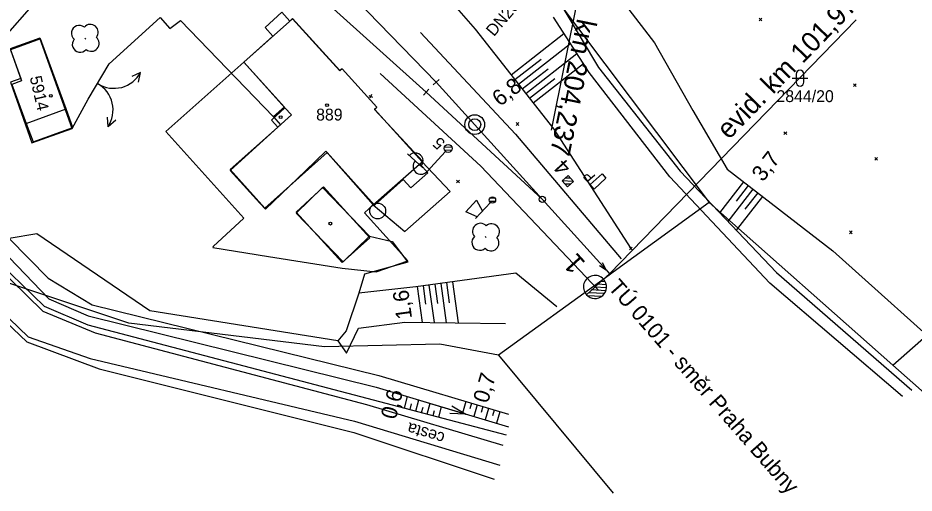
# Model space of a CAD drawing. Extents: x -800194 to -799078, y -1007177 to -1006597.
# Drawn here: x -799787.9 to -799674.6, y -1007068 to -1007007.9 of the extents above; entities that cross this region are included whole.
import ezdxf

# ---------------------------------------------------------------- set-up
doc = ezdxf.new("R2010")
doc.units = 0
for name, color, linetype in [('02_Osa_koleje', 7, 'Continuous'), ('_návrh', 7, 'Continuous'), ('Vrstva 11', 7, 'Continuous'), ('Vrstva 13', 7, 'Continuous'), ('Vrstva 17', 7, 'Continuous'), ('Vrstva 2', 7, 'Continuous'), ('Vrstva 23', 7, 'Continuous'), ('Vrstva 25', 7, 'Continuous'), ('Vrstva 3', 7, 'Continuous'), ('Vrstva 33', 7, 'Continuous'), ('Vrstva 4', 7, 'Continuous'), ('Vrstva 43', 7, 'Continuous'), ('Vrstva 48', 7, 'Continuous'), ('Vrstva 49', 7, 'Continuous'), ('Vrstva 5', 7, 'Continuous'), ('Vrstva 50', 7, 'Continuous'), ('Vrstva 51', 7, 'Continuous'), ('Vrstva 55', 7, 'Continuous'), ('Vrstva 56', 7, 'Continuous'), ('Vrstva 57', 7, 'Continuous'), ('Vrstva 58', 7, 'Continuous'), ('Vrstva 59', 7, 'Continuous'), ('Vrstva 7', 7, 'Continuous')]:
    doc.layers.add(name, color=color, linetype=linetype)

msp = doc.modelspace()

# ---------------------------------------------------------------- linework, layer by layer
at = {"layer": '_návrh'}
for points in [[(-799821.59, -1006948.01), (-799811.06, -1006954.32), (-799803.75, -1006958.71), (-799793.94, -1006964.58), (-799784.22, -1006971.67), (-799782.91, -1006972.63), (-799767.42, -1006984.72), (-799752.33, -1006998.17), (-799735.03, -1007016), (-799721.62, -1007030.81), (-799713.56, -1007039.73), (-799713.11, -1007040.22)], [(-799820.76, -1006954), (-799803, -1006964.74), (-799786.68, -1006975.32), (-799769.88, -1006987.81), (-799754.74, -1007000.64), (-799736.31, -1007017.26), (-799721.62, -1007030.81)]]:
    msp.add_lwpolyline(points, dxfattribs=at)
at = {"layer": 'Vrstva 11'}
for p, q in [((-799717.7, -1007028.56), (-799719.11, -1007028.49)), ((-799718.09, -1007028.91), (-799718.75, -1007028.88)), ((-799718.05, -1007028.16), (-799718.72, -1007028.13))]:
    msp.add_line(p, q, dxfattribs=at)
msp.add_lwpolyline([(-799718.44, -1007029.23), (-799719.11, -1007028.48), (-799718.37, -1007027.81), (-799717.69, -1007028.56)], close=True, dxfattribs=at)
at = {"layer": 'Vrstva 13'}
msp.add_line((-799737.02, -1007056.24), (-799731.27, -1007057.97), dxfattribs=at)
for points in [[(-799805.07, -1007021.46), (-799784.01, -1007043.38), (-799779.03, -1007045.56), (-799742.64, -1007054.55), (-799725.89, -1007059.59)], [(-799733.04, -1007056.92), (-799731.27, -1007057.97), (-799733.33, -1007057.88)]]:
    msp.add_lwpolyline(points, dxfattribs=at)
at = {"layer": 'Vrstva 17'}
for p, q in [((-799779.06, -1007018.13), (-799776.39, -1007013.67)), ((-799781.07, -1007021.85), (-799779.06, -1007018.13)), ((-799738.62, -1007038.76), (-799744.11, -1007040.3))]:
    msp.add_line(p, q, dxfattribs=at)
for points in [[(-799828.95, -1007006.88), (-799820.58, -1007016.71), (-799786.81, -1007048.82), (-799777.64, -1007052.25), (-799745.45, -1007060.29), (-799727.71, -1007066.19)], [(-799776.39, -1007013.67), (-799769.93, -1007007.83), (-799768.72, -1007009.2), (-799767.36, -1007008.22), (-799755.62, -1007020.4)], [(-799744.11, -1007040.3), (-799744.8, -1007042.69), (-799746.42, -1007047.46), (-799747.49, -1007048.69), (-799771.23, -1007044.93), (-799785.53, -1007035.2), (-799789.01, -1007035.75), (-799804.25, -1007020.27), (-799801.55, -1007019.07), (-799803.93, -1007010.19)], [(-799772.68, -1007016.01), (-799772.41, -1007014.78), (-799773.52, -1007015.27)], [(-799775.56, -1007020.82), (-799776.52, -1007021.64), (-799776.61, -1007020.42)], [(-799743.45, -1007035.49), (-799740.6, -1007036.15), (-799738.62, -1007038.76)]]:
    msp.add_lwpolyline(points, dxfattribs=at)
for centre, start, end in [((-799775.78, -1007012.95), 238.0469, 331.5667), ((-799779.72, -1007019.53), 326.5964, 60.1163)]:
    msp.add_arc(centre, 3.83, start, end, dxfattribs=at)
at = {"layer": 'Vrstva 2'}
for p, q in [((-799713.11, -1007040.22), (-799681.94, -1007008.13)), ((-799735.4, -1007016.33), (-799734.66, -1007015.66)), ((-799735.97, -1007016.89), (-799736.65, -1007017.63)), ((-799713.88, -1007040.92), (-799713.11, -1007040.22)), ((-799716.05, -1007042.88), (-799713.88, -1007040.92)), ((-799713.67, -1007041.23), (-799714.19, -1007041.2)), ((-799713.58, -1007042.37), (-799715.39, -1007042.28)), ((-799713.51, -1007041.99), (-799714.99, -1007041.92)), ((-799713.53, -1007041.61), (-799714.59, -1007041.56)), ((-799716.05, -1007042.88), (-799716.05, -1007042.88)), ((-799714.14, -1007043.1), (-799715.91, -1007043.02)), ((-799713.77, -1007042.74), (-799715.79, -1007042.64))]:
    msp.add_line(p, q, dxfattribs=at)
msp.add_lwpolyline([(-799714.4, -1007039.18), (-799713.56, -1007039.73), (-799714.01, -1007038.84)], dxfattribs=at)
msp.add_circle((-799721.62, -1007030.81), 0.4, dxfattribs=at)
for start, end in [(42.0718, 222.5413), (222.1613, 42.1222)]:
    msp.add_arc((-799714.96, -1007041.9), 1.46, start, end, dxfattribs=at)
at = {"layer": 'Vrstva 23'}
for points in [[(-799756.7, -1007031.95), (-799748.82, -1007024.88), (-799742.83, -1007031.56), (-799739.2, -1007028.31), (-799738.26, -1007029.36), (-799736.11, -1007027.47), (-799737.08, -1007026.37), (-799736.71, -1007026.05), (-799742.83, -1007019.45), (-799742.53, -1007019.18), (-799746.94, -1007014.31), (-799747.2, -1007014.54), (-799753.19, -1007007.93), (-799753.56, -1007008.27), (-799754.56, -1007007.16), (-799756.67, -1007009.07), (-799755.68, -1007010.17), (-799759.34, -1007013.45), (-799754.23, -1007019.15), (-799755.62, -1007020.4), (-799754.74, -1007021.39), (-799761.08, -1007027.06), (-799756.7, -1007031.95)], [(-799785.14, -1007010.44), (-799788.91, -1007011.78), (-799787.56, -1007015.55), (-799788.88, -1007016.02), (-799786.16, -1007023.66), (-799781.07, -1007021.85), (-799785.14, -1007010.44)], [(-799746.8, -1007038.73), (-799743.45, -1007035.49), (-799749.4, -1007029.33), (-799752.76, -1007032.58), (-799746.8, -1007038.73)]]:
    msp.add_lwpolyline(points, dxfattribs=at)
at = {"layer": 'Vrstva 25'}
for p, q in [((-799733.05, -1007024.22), (-799734, -1007024.26)), ((-799736.74, -1007026.84), (-799738.65, -1007025.08)), ((-799733.86, -1007024.75), (-799736.23, -1007027.32)), ((-799733.07, -1007024.59), (-799733.95, -1007024.63))]:
    msp.add_line(p, q, dxfattribs=at)
msp.add_circle((-799733.52, -1007024.38), 0.5, dxfattribs=at)
for centre, start, end in [((-799737.69, -1007025.95), 316.6332, 138.0383), ((-799736.96, -1007026.64), 137.3357, 317.3357)]:
    msp.add_arc(centre, 1, start, end, dxfattribs=at)
at = {"layer": 'Vrstva 3'}
msp.add_line((-799769.88, -1006987.81), (-799828.64, -1007054.5), dxfattribs=at)
at = {"layer": 'Vrstva 33'}
for p, q in [((-799731.31, -1007032.4), (-799729.95, -1007030.92)), ((-799730.07, -1007033.26), (-799728.18, -1007031.21)), ((-799729.95, -1007030.92), (-799729.19, -1007032.31)), ((-799727.59, -1007030.68), (-799728.27, -1007030.7)), ((-799727.56, -1007031.08), (-799728.26, -1007031.1)), ((-799729.86, -1007033.04), (-799731.31, -1007032.4))]:
    msp.add_line(p, q, dxfattribs=at)
for points in [[(-799716.27, -1007028.19), (-799716.34, -1007028.04), (-799716.26, -1007027.82), (-799716.18, -1007027.75), (-799715.95, -1007027.69), (-799715.81, -1007027.78)], [(-799714.99, -1007027.74), (-799715.92, -1007028.58)], [(-799715.81, -1007027.78), (-799715.46, -1007028.16)], [(-799715.92, -1007028.58), (-799716.27, -1007028.19)]]:
    msp.add_lwpolyline(points, dxfattribs=at)
msp.add_lwpolyline([(-799715.07, -1007029.52), (-799715.56, -1007028.96), (-799714.07, -1007027.61), (-799713.57, -1007028.16)], close=True, dxfattribs=at)
msp.add_circle((-799727.92, -1007030.9), 0.401, dxfattribs=at)
at = {"layer": 'Vrstva 4'}
for points in [[(-799737.02, -1007009.7), (-799725.03, -1007022.56), (-799711.65, -1007038.33)], [(-799742.12, -1007014.91), (-799729.41, -1007026.63), (-799714.56, -1007042.27)]]:
    msp.add_lwpolyline(points, dxfattribs=at)
at = {"layer": 'Vrstva 43'}
msp.add_circle((-799742.43, -1007032.29), 1, dxfattribs=at)
at = {"layer": 'Vrstva 48'}
for p, q in [((-799725.54, -1007015.08), (-799718.88, -1007009.85)), ((-799724.62, -1007016.26), (-799718.06, -1007011.11)), ((-799725.08, -1007015.67), (-799721.77, -1007013.08)), ((-799723.69, -1007017.44), (-799717.24, -1007012.38)), ((-799722.77, -1007018.62), (-799716.42, -1007013.64)), ((-799724.16, -1007016.85), (-799720.9, -1007014.3)), ((-799723.23, -1007018.03), (-799720.03, -1007015.52)), ((-799696.17, -1007028.6), (-799699.2, -1007032.52)), ((-799694.99, -1007029.52), (-799698.16, -1007033.62)), ((-799695.58, -1007029.06), (-799697.13, -1007031.06)), ((-799694.39, -1007029.98), (-799696.01, -1007032.07)), ((-799693.8, -1007030.44), (-799697.11, -1007034.72)), ((-799733.72, -1007041.35), (-799733.38, -1007043.89)), ((-799732.98, -1007041.25), (-799732.28, -1007046.44)), ((-799737.44, -1007041.85), (-799736.82, -1007046.39)), ((-799736.69, -1007041.75), (-799736.38, -1007044.08)), ((-799735.95, -1007041.65), (-799735.31, -1007046.41)), ((-799735.21, -1007041.55), (-799734.88, -1007043.98)), ((-799734.46, -1007041.45), (-799733.79, -1007046.42)), ((-799739.06, -1007057.21), (-799738.67, -1007055.75)), ((-799738.33, -1007057.41), (-799738.14, -1007056.68)), ((-799737.61, -1007057.6), (-799737.23, -1007056.18)), ((-799736.88, -1007057.79), (-799736.7, -1007057.09)), ((-799736.16, -1007057.98), (-799735.8, -1007056.61)), ((-799734.71, -1007058.36), (-799734.36, -1007057.04)), ((-799731.29, -1007056.39), (-799731.72, -1007057.84)), ((-799730.57, -1007056.61), (-799730.79, -1007057.33)), ((-799729.85, -1007056.82), (-799730.28, -1007058.27)), ((-799729.13, -1007057.03), (-799729.35, -1007057.76)), ((-799728.42, -1007057.25), (-799728.85, -1007058.7)), ((-799735.43, -1007058.17), (-799735.25, -1007057.5)), ((-799727.7, -1007057.46), (-799727.91, -1007058.19)), ((-799726.98, -1007057.68), (-799727.41, -1007059.13))]:
    msp.add_line(p, q, dxfattribs=at)
at = {"layer": 'Vrstva 49'}
for p, q in [((-799694.21, -1007007.89), (-799693.85, -1007008.25)), ((-799694.21, -1007008.25), (-799693.85, -1007007.89)), ((-799682.29, -1007016.19), (-799681.94, -1007016.54)), ((-799682.29, -1007016.54), (-799681.94, -1007016.19)), ((-799743.22, -1007017.57), (-799743.43, -1007018.03)), ((-799743.55, -1007017.7), (-799743.1, -1007017.9)), ((-799724.92, -1007021.1), (-799724.57, -1007021.46)), ((-799724.92, -1007021.46), (-799724.57, -1007021.1)), ((-799720.16, -1007021.94), (-799710.42, -1007037.04)), ((-799691.07, -1007022.28), (-799690.71, -1007022.63)), ((-799691.07, -1007022.63), (-799690.71, -1007022.28)), ((-799679.59, -1007025.51), (-799679.23, -1007025.86)), ((-799679.59, -1007025.86), (-799679.23, -1007025.51)), ((-799732.47, -1007028.39), (-799732.11, -1007028.74)), ((-799732.47, -1007028.74), (-799732.11, -1007028.39)), ((-799682.8, -1007034.8), (-799682.45, -1007035.16)), ((-799682.8, -1007035.16), (-799682.45, -1007034.8)), ((-799710.6, -1007036.86), (-799710.25, -1007037.22)), ((-799710.6, -1007037.22), (-799710.25, -1007036.86))]:
    msp.add_line(p, q, dxfattribs=at)
for points in [[(-799823.43, -1006985.38), (-799817.84, -1006990.05), (-799815.5, -1006993.97), (-799810.13, -1006998.91), (-799803.93, -1007010.19), (-799801.55, -1007019.07), (-799804.25, -1007020.27), (-799789.01, -1007035.75), (-799784.1, -1007040.77), (-799778.54, -1007044.17), (-799742.31, -1007053.11), (-799725.9, -1007058)], [(-799823.43, -1006985.38), (-799822.82, -1006995.38), (-799809.85, -1007012.44), (-799805.07, -1007021.46), (-799784.01, -1007043.38), (-799779.03, -1007045.56), (-799742.64, -1007054.55), (-799725.89, -1007059.59)], [(-799822.82, -1006995.38), (-799817.69, -1007012.45), (-799816.63, -1007013.29), (-799784.59, -1007044.32), (-799779.07, -1007046.68), (-799743, -1007056.17), (-799726.2, -1007060.6)], [(-799716.25, -1006997.26), (-799711.44, -1007004.24), (-799711.11, -1007006.25), (-799707.44, -1007011.02), (-799702.58, -1007019.59), (-799698.24, -1007027), (-799684.87, -1007037.35), (-799668.9, -1007051.67)], [(-799733.04, -1007005.94), (-799730.09, -1007009.29), (-799720.16, -1007021.94)], [(-799718.91, -1007006.79), (-799714.52, -1007014.16), (-799704.21, -1007027.24), (-799692.02, -1007040.08), (-799674.89, -1007054.95)], [(-799676.08, -1007055.76), (-799692.87, -1007041.41), (-799705.48, -1007027.95), (-799715.68, -1007014.78), (-799720.21, -1007007.79)], [(-799719.8, -1007044.43), (-799724.97, -1007040.17), (-799737.6, -1007041.88), (-799744.8, -1007042.69), (-799746.42, -1007047.46), (-799747.49, -1007048.69), (-799746.37, -1007050.25)], [(-799746.37, -1007050.25), (-799744.87, -1007047.1), (-799739.02, -1007046.37), (-799726.29, -1007046.5)]]:
    msp.add_lwpolyline(points, dxfattribs=at)
at = {"layer": 'Vrstva 5'}
msp.add_line((-799720.48, -1007022.09), (-799714.57, -1006992.8), dxfattribs=at)
at = {"layer": 'Vrstva 50'}
for p, q in [((-799779.46, -1007010.42), (-799779.35, -1007010.51)), ((-799728.74, -1007035.63), (-799728.83, -1007035.53))]:
    msp.add_line(p, q, dxfattribs=at)
for centre, start, end in [((-799780.17, -1007009.81), 49.7024, 229.7024), ((-799778.76, -1007009.69), 319.7024, 139.7024), ((-799780.05, -1007011.22), 139.7024, 319.7024), ((-799778.65, -1007011.1), 229.7024, 49.7024), ((-799729.45, -1007034.85), 42.1413, 222.1413), ((-799728.04, -1007034.92), 312.1413, 132.1413), ((-799729.52, -1007036.26), 132.1413, 312.1413), ((-799728.11, -1007036.33), 222.1413, 42.1413)]:
    msp.add_arc(centre, 1, start, end, dxfattribs=at)
at = {"layer": 'Vrstva 51'}
for points in [[(-799817.05, -1006918.97), (-799812.09, -1006931.54), (-799815.67, -1006943.13), (-799826.02, -1006959.48), (-799831.21, -1006965.51), (-799832.48, -1006972.31), (-799831.13, -1006986.86), (-799828.08, -1006983.27), (-799821.9, -1006976.03), (-799813.15, -1006974.92), (-799805.94, -1006982.79), (-799808.36, -1006984.77), (-799815.09, -1006977.55), (-799820.32, -1006978.43), (-799823.43, -1006985.38), (-799830.08, -1006997.73), (-799819.52, -1007011.7), (-799817.35, -1007013.08), (-799784.79, -1007044.96), (-799778.17, -1007047.69), (-799743.86, -1007056.78), (-799726.63, -1007061.89)], [(-799842.2, -1006982.51), (-799833.07, -1007000.36), (-799821.84, -1007014.25), (-799786.62, -1007048.21), (-799778.77, -1007050.96), (-799745.38, -1007058.85), (-799727.01, -1007064.42)]]:
    msp.add_lwpolyline(points, dxfattribs=at)
at = {"layer": 'Vrstva 55'}
for p, q in [((-799700.54, -1007031.23), (-799677.3, -1007051.77)), ((-799677.3, -1007051.77), (-799665.73, -1007041.59)), ((-799727.16, -1007050.52), (-799712.65, -1007067.97))]:
    msp.add_line(p, q, dxfattribs=at)
for points in [[(-799733.28, -1006992.13), (-799723.72, -1007000.38), (-799700.54, -1007031.23)], [(-799753.19, -1007008), (-799759.37, -1007013.49), (-799769.21, -1007022.23), (-799759.34, -1007033.19), (-799763.24, -1007036.79), (-799763.26, -1007036.9), (-799756.25, -1007038.04), (-799746.93, -1007039.54), (-799742.61, -1007039.98), (-799738.64, -1007038.58), (-799744.1, -1007032.52), (-799742.99, -1007031.53), (-799739, -1007034.9), (-799733.28, -1007029.82), (-799736.83, -1007026.06), (-799742.84, -1007019.43), (-799742.54, -1007019.16), (-799746.93, -1007014.32), (-799747.23, -1007014.58), (-799749.47, -1007012.1), (-799753.19, -1007008)], [(-799788.68, -1007016.29), (-799786.88, -1007021.22), (-799785.99, -1007023.53), (-799780.99, -1007021.72), (-799781.84, -1007019.38), (-799785.05, -1007010.5), (-799788.88, -1007011.9), (-799787.45, -1007015.84), (-799788.68, -1007016.29)], [(-799727.16, -1007050.52), (-799734.57, -1007049.13), (-799749.18, -1007049.49), (-799773.9, -1007046.46), (-799791.91, -1007040.49), (-799811.13, -1007032.26)], [(-799700.54, -1007031.23), (-799712.19, -1007039.67), (-799713.65, -1007040.73), (-799727.16, -1007050.52)], [(-799677.3, -1007051.77), (-799624.44, -1007098.49), (-799623.27, -1007096.82)]]:
    msp.add_lwpolyline(points, dxfattribs=at)
at = {"layer": 'Vrstva 56'}
for p, q in [((-799754.17, -1007019.25), (-799759.37, -1007013.49)), ((-799786.88, -1007021.22), (-799781.84, -1007019.38)), ((-799755.87, -1007020.79), (-799754.17, -1007019.25)), ((-799754.17, -1007019.25), (-799753.35, -1007020.15)), ((-799755.06, -1007021.69), (-799755.87, -1007020.79)), ((-799753.35, -1007020.15), (-799755.06, -1007021.69)), ((-799761.09, -1007027.15), (-799755.06, -1007021.69)), ((-799751.58, -1007027.23), (-799748.98, -1007024.74)), ((-799748.98, -1007024.74), (-799742.99, -1007031.53)), ((-799742.99, -1007031.53), (-799736.83, -1007026.06)), ((-799757.32, -1007031.32), (-799761.09, -1007027.15)), ((-799756.64, -1007032.07), (-799751.58, -1007027.23)), ((-799752.74, -1007032.43), (-799749.3, -1007029.24)), ((-799749.3, -1007029.24), (-799743.44, -1007035.69)), ((-799756.64, -1007032.07), (-799757.32, -1007031.32)), ((-799746.94, -1007038.81), (-799752.74, -1007032.43)), ((-799746.94, -1007038.81), (-799743.44, -1007035.69))]:
    msp.add_line(p, q, dxfattribs=at)
at = {"layer": 'Vrstva 58'}
for p, q in [((-799689.54, -1007014.99), (-799689.54, -1007015.99)), ((-799688.54, -1007015.99), (-799688.54, -1007014.99)), ((-799690.04, -1007015.49), (-799688.04, -1007015.49))]:
    msp.add_line(p, q, dxfattribs=at)
for centre, start, end in [((-799689.04, -1007014.99), 0, 180), ((-799689.04, -1007015.99), 180, 359.9879)]:
    msp.add_arc(centre, 0.5, start, end, dxfattribs=at)
at = {"layer": 'Vrstva 59'}
for centre in [(-799783.77, -1007017.72), (-799748.84, -1007018.92), (-799754.7, -1007020.42), (-799748.42, -1007033.89)]:
    msp.add_circle(centre, 0.175, dxfattribs=at)
at = {"layer": 'Vrstva 7'}
for radius in [1.25, 0.752]:
    msp.add_circle((-799730.16, -1007021.37), radius, dxfattribs=at)

# ---------------------------------------------------------------- texts
at = {"layer": '02_Osa_koleje'}
msp.add_text('TÚ 0101 - směr Praha Bubny', height=2, rotation=311.117, dxfattribs=at).set_placement((-799713.38, -1007042.03))
at = {"layer": 'Vrstva 11'}
msp.add_text('4', height=2, rotation=132.1416, dxfattribs=at).set_placement((-799717.86, -1007026.67))
at = {"layer": 'Vrstva 2'}
for s, rotation, p in [('evid. km 101,978', 45.831, (-799698.03, -1007023.35)), ('1', 132.1418, (-799716.05, -1007038.83))]:
    msp.add_text(s, height=2.5, rotation=rotation, dxfattribs=at).set_placement(p)
at = {"layer": 'Vrstva 25'}
msp.add_text('5', height=1.5, rotation=137.3357, dxfattribs=at).set_placement((-799733.79, -1007023.57))
at = {"layer": 'Vrstva 43'}
msp.add_text('DN200', height=1.5, rotation=49.5752, dxfattribs=at).set_placement((-799727.74, -1007010.31))
at = {"layer": 'Vrstva 48'}
for s, rotation, p in [('6,8', 38.126, (-799726.98, -1007019.15)), ('3,7', 52.2686, (-799693.73, -1007028.7)), ('1,6', 97.6781, (-799738.08, -1007045.85)), ('0,7', 73.4318, (-799728.51, -1007056.7)), ('0,6', 75.2247, (-799740.16, -1007058.75))]:
    msp.add_text(s, height=2, rotation=rotation, dxfattribs=at).set_placement(p)
at = {"layer": 'Vrstva 5'}
for s, rotation, p in [('km 204,169', 244.8436, (-799789.02, -1006993.66)), ('km 204,237', 258.5895, (-799717.2, -1007007.87))]:
    msp.add_text(s, height=2.5, rotation=rotation, dxfattribs=at).set_placement(p)
at = {"layer": 'Vrstva 51'}
msp.add_text('cesta', height=1.5, rotation=163.1272, dxfattribs=at).set_placement((-799733.84, -1007060.41))
at = {"layer": 'Vrstva 57'}
msp.add_text('5914', height=1.5, rotation=283, dxfattribs=at).set_placement((-799786.44, -1007015.38))
for s, p in [('2844/20', (-799692.02, -1007018.52)), ('889', (-799750.22, -1007020.85))]:
    msp.add_text(s, height=1.5, dxfattribs=at).set_placement(p)

doc.saveas('drawing.dxf')
